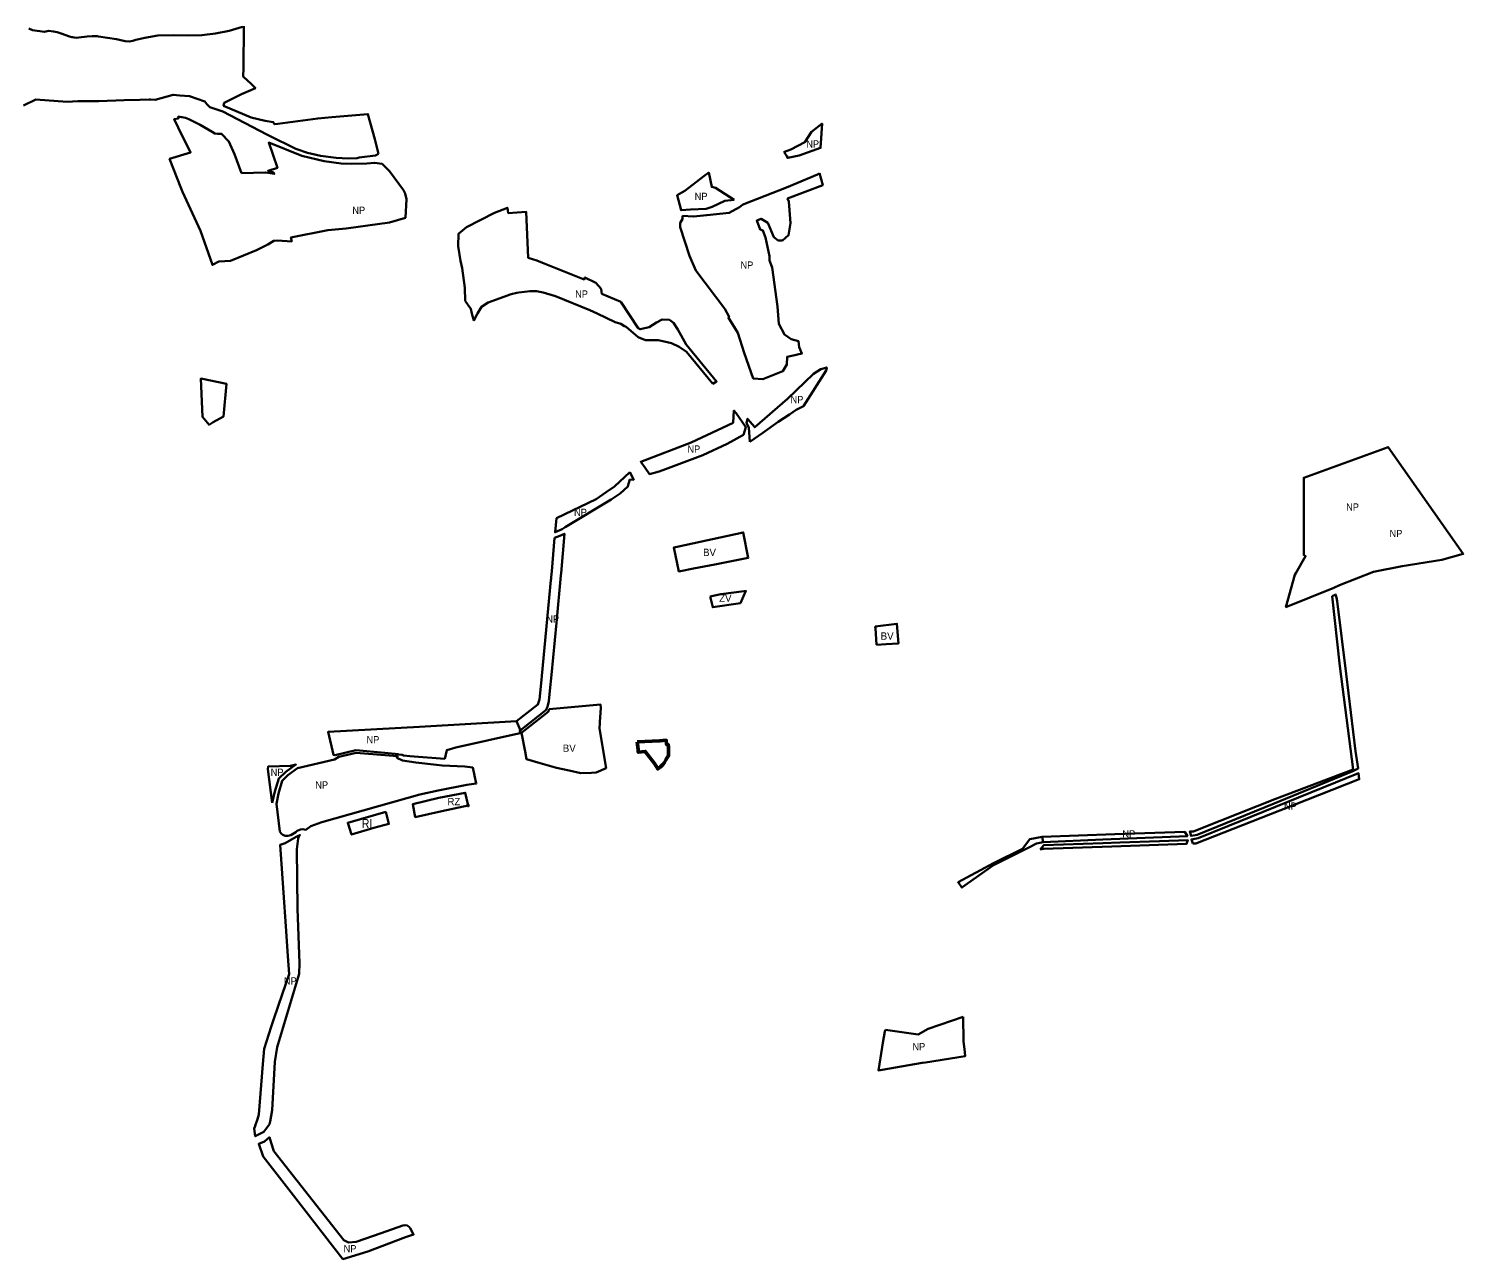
# Model space of a CAD drawing. Extents: x -650276 to -642489, y -1074311 to -1066658.
# Drawn here: x -644867 to -642489, y -1070907 to -1068866 of the extents above; entities that cross this region are included whole.
import ezdxf

# ---------------------------------------------------------------- set-up
doc = ezdxf.new("R2010")
doc.units = 0
doc.header["$LTSCALE"] = 4.8
doc.header["$PDMODE"] = 32
doc.header["$PDSIZE"] = 2.4
for name, color, linetype, lineweight in [('15', 7, 'Continuous', 35), ('3', 7, 'Continuous', 35), ('40', 7, 'Continuous', 35), ('48', 7, 'Continuous', 35), ('6', 7, 'Continuous', 35), ('60', 7, 'Continuous', 53), ('8', 7, 'Continuous', 35)]:
    doc.layers.add(name, color=color, linetype=linetype, lineweight=lineweight)
doc.layers.add('62', color=7, linetype='Continuous')

msp = doc.modelspace()

# ---------------------------------------------------------------- linework, layer by layer
at = {"layer": '15', "lineweight": 13}
for points in [[(-643461.327, -1069887.84), (-643445.37, -1069886.7), (-643425.253, -1069885.25), (-643427.6, -1069852.59), (-643463.51, -1069857.44)], [(-643463.51, -1069857.44), (-643463.31, -1069860.18), (-643461.327, -1069887.84)]]:
    msp.add_lwpolyline(points, dxfattribs=at)
at = {"layer": '3'}
for points in [[(-643791.88, -1069725.25), (-643797.75, -1069726.51), (-643789.3, -1069766.05), (-643786.35, -1069765.46), (-643764.94, -1069761.27), (-643729.34, -1069754.3), (-643674.3, -1069743.53), (-643682.61, -1069701.16)], [(-643461.327, -1069887.84), (-643445.37, -1069886.7), (-643425.253, -1069885.25), (-643427.6, -1069852.59), (-643463.51, -1069857.44), (-643463.31, -1069860.18)], [(-643920.84, -1070026.46), (-643920.29, -1070017.73), (-643920.16, -1070015.69), (-643918.69, -1069992.23), (-643918.88, -1069986.82), (-644004.06, -1069994.59), (-644005.92, -1069998.62), (-644044.7, -1070029.04), (-644050.12, -1070033.64), (-644044.18, -1070064.43), (-644041.71, -1070077.29), (-644022.77, -1070082.66), (-643991.99, -1070091.37), (-643971.03, -1070095.79), (-643951.99, -1070100.35), (-643933.96, -1070100.18), (-643926.33, -1070099.5), (-643909.87, -1070091.95)]]:
    msp.add_lwpolyline(points, close=True, dxfattribs=at)
at = {"layer": '40'}
msp.add_lwpolyline([(-643737.47, -1069807.24), (-643733.02, -1069825.4), (-643687.2, -1069818.8), (-643680.15, -1069803.22), (-643678.02, -1069798.52), (-643680.83, -1069798.86), (-643719.42, -1069803.49)], close=True, dxfattribs=at)
at = {"layer": '48'}
msp.add_line((-644015.12, -1069254.24), (-644024.93, -1069250.23), dxfattribs=at)
for points in [[(-644783.84, -1068880.69), (-644787.7, -1068880.94), (-644791.66, -1068880.72), (-644794.33, -1068880.25), (-644795.57, -1068880.03), (-644799.27, -1068878.92), (-644813.52, -1068873.69), (-644819.79, -1068871.79), (-644826.24, -1068870.62), (-644834.48, -1068869.6), (-644840.86, -1068870.9), (-644861.04, -1068868.43), (-644867.05, -1068865.58)], [(-644512.71, -1068863.06), (-644534.67, -1068869.62), (-644557.21, -1068874.19), (-644580.06, -1068876.69), (-644602.97, -1068877.11), (-644626.34, -1068876.48), (-644653.09, -1068877.33), (-644674.5, -1068880.97), (-644689.63, -1068884.43), (-644694.39, -1068886.08), (-644700.83, -1068886.97), (-644707.32, -1068886.63), (-644721.29, -1068883.2), (-644751.36, -1068878.76), (-644753.71, -1068878.41), (-644761.63, -1068878.43), (-644770.17, -1068879.01), (-644783.84, -1068880.69)], [(-644286.94, -1069073.19), (-644293.51, -1069049.01), (-644304.6, -1069007.55), (-644364.53, -1069012.83), (-644387.91, -1069014.64), (-644453.95, -1069023.63), (-644459.67, -1069024.41), (-644461.74, -1069020.83), (-644475.09, -1069018.99), (-644498.28, -1069013.19), (-644544.02, -1068993.75), (-644543.05, -1068988.64), (-644523.4, -1068978.98), (-644519.61, -1068977.02), (-644514.16, -1068974.62), (-644491.31, -1068964.35), (-644496.63, -1068959.11), (-644498.8, -1068956.97), (-644503.61, -1068952.56), (-644511.47, -1068945.37), (-644510.75, -1068931.16), (-644510.37, -1068861.95)], [(-644657.61, -1068983.91), (-644627.41, -1068975.6), (-644616.36, -1068976.86), (-644600.67, -1068977.77), (-644575.29, -1068986.48), (-644572.05, -1068991.08), (-644567.09, -1068996.26), (-644545.54, -1069003.12), (-644472.37, -1069041.44), (-644468.95, -1069043.11), (-644424.01, -1069065.01), (-644404.96, -1069071.76), (-644383.55, -1069076.57), (-644357.4, -1069079.84), (-644337.6, -1069081.29), (-644322.55, -1069080.62), (-644319.2, -1069079.82), (-644292.27, -1069076.05), (-644286.94, -1069073.19)], [(-644875.57, -1068993.47), (-644855.56, -1068983.38), (-644803.31, -1068986.97), (-644785.78, -1068986.13), (-644761.88, -1068986.27), (-644750.67, -1068986.34), (-644708.6, -1068984.54), (-644683, -1068984.03), (-644667.57, -1068983.47), (-644665.41, -1068983.39), (-644657.61, -1068983.91)], [(-644619.1, -1069011.81), (-644618.8, -1069014.7), (-644625.69, -1069015.84)], [(-644625.69, -1069015.84), (-644619.54, -1069029.55), (-644598.81, -1069071.02)], [(-644583.05, -1069025.29), (-644601.43, -1069015.74), (-644607.16, -1069013.56), (-644619.1, -1069011.81)], [(-644553.62, -1069040.53), (-644558.56, -1069039.86), (-644563.19, -1069037.21), (-644583.05, -1069025.29)], [(-644535.13, -1069053.18), (-644547.31, -1069040.11), (-644553.62, -1069040.53)], [(-644598.81, -1069071.02), (-644633.66, -1069082), (-644614.41, -1069131.08), (-644612.3, -1069136.45), (-644582.29, -1069201.27), (-644562.47, -1069257.56), (-644552.01, -1069252.24), (-644541.83, -1069251.66), (-644532.71, -1069251.12), (-644489.27, -1069233.04), (-644470.64, -1069224), (-644460.97, -1069217.61)], [(-644514.47, -1069105.62), (-644525.83, -1069073.84), (-644535.13, -1069053.18)], [(-644281.26, -1069090.19), (-644293.62, -1069088.17), (-644306.29, -1069089.37), (-644331.44, -1069090), (-644349.32, -1069089.22), (-644377.36, -1069085.89), (-644414.04, -1069076.75), (-644469.28, -1069054.8), (-644454.75, -1069096.51)], [(-644454.75, -1069096.51), (-644470.37, -1069101.55), (-644461.01, -1069104.36), (-644459.82, -1069106.73), (-644474.33, -1069104.22), (-644514.47, -1069105.62)], [(-644242.48, -1069179.49), (-644240.67, -1069148.58), (-644243.14, -1069139.47), (-644245.65, -1069133.66), (-644269.11, -1069102.31), (-644281.26, -1069090.19)], [(-643697.29, -1069149.7), (-643728.49, -1069129.95), (-643734.75, -1069128.3), (-643739.66, -1069104.58), (-643747.75, -1069110.71), (-643779.31, -1069134.63), (-643784.55, -1069137.77), (-643792.04, -1069142.27), (-643785.6, -1069166.98), (-643769.71, -1069166.04)], [(-643555.98, -1069105.57), (-643559.5, -1069107.98), (-643610.81, -1069129.04), (-643681.63, -1069157.04), (-643683.68, -1069157.86), (-643688.91, -1069162.16), (-643705.7, -1069171.37), (-643743.11, -1069175.08), (-643764.86, -1069177.58), (-643782.92, -1069176.24)], [(-643607.02, -1069152.34), (-643609.08, -1069147.64), (-643550.79, -1069125.24), (-643555.98, -1069105.57)], [(-644024.93, -1069250.23), (-644038.83, -1069245.65), (-644042.37, -1069169.77), (-644071.97, -1069171.72), (-644073.35, -1069162.84), (-644094.79, -1069171.27)], [(-643769.71, -1069166.04), (-643743.99, -1069164.43), (-643733.83, -1069161.46), (-643712.74, -1069151.46), (-643697.29, -1069149.7)], [(-643707.23, -1069344.52), (-643691.6, -1069370.3), (-643681.09, -1069403.24), (-643665.87, -1069446.1), (-643650.28, -1069446.91), (-643616.78, -1069433.81), (-643610.18, -1069422.91), (-643609.6, -1069409.99), (-643601.9, -1069408.43), (-643585.19, -1069404.76), (-643589.52, -1069393.88), (-643590.89, -1069383.9), (-643602.92, -1069380.53), (-643614.35, -1069373.28), (-643623.28, -1069355.47), (-643625.9, -1069326.77), (-643634.56, -1069262.02), (-643639.23, -1069250.38), (-643638.72, -1069242.94), (-643645.61, -1069212.25), (-643649.84, -1069200.4), (-643654.57, -1069198.77), (-643660.22, -1069184.11), (-643653.05, -1069180.98), (-643641.84, -1069187.68), (-643631.66, -1069211.67), (-643624.38, -1069217.27), (-643617.64, -1069217), (-643607.37, -1069208.43), (-643604.38, -1069188.48), (-643607.02, -1069152.34)], [(-644460.97, -1069217.61), (-644454.87, -1069217.05), (-644430.91, -1069218.82), (-644432.53, -1069212.02), (-644371.08, -1069199.84), (-644340.83, -1069197.13), (-644268.7, -1069187.42), (-644242.48, -1069179.49)], [(-644094.79, -1069171.27), (-644141.24, -1069195.17), (-644154.36, -1069206.06), (-644155.37, -1069226.72), (-644151.11, -1069250.7), (-644148.22, -1069263.22), (-644144.05, -1069295.67)], [(-643782.92, -1069176.24), (-643783.2, -1069181.85), (-643786.97, -1069188.11), (-643786.89, -1069195.02), (-643771.86, -1069242.77), (-643761.21, -1069267.12), (-643712.78, -1069330.24)], [(-643732.705, -1069454.79), (-643726.74, -1069450.72), (-643777.27, -1069389.71), (-643791.02, -1069364.54), (-643798.1, -1069353.51), (-643804.83, -1069348.99), (-643817.06, -1069348.14), (-643826.21, -1069352.92), (-643838.69, -1069360.79), (-643853.56, -1069364.44), (-643856.43, -1069362.68), (-643885.63, -1069318.72), (-643916.78, -1069305.89), (-643917.36, -1069302.04), (-643918.08, -1069297.33), (-643926.74, -1069287.37), (-643944.89, -1069278.32), (-643946.16, -1069281.84), (-644015.12, -1069254.24)], [(-644144.05, -1069295.67), (-644143.54, -1069317.05), (-644138.55, -1069324.23), (-644134.15, -1069330.45), (-644132.52, -1069338.02), (-644129.09, -1069349.83), (-644123.21, -1069338.41), (-644116.33, -1069327.36), (-644105.5, -1069320.03), (-644067.08, -1069306.15), (-644058.05, -1069304.02), (-644054.35, -1069303.55)], [(-644054.35, -1069303.55), (-644035.89, -1069301.02), (-644025.24, -1069301.38), (-644014.19, -1069303.36), (-643993.91, -1069309.57), (-643936.87, -1069332.93), (-643924.42, -1069338.29), (-643894.84, -1069352.76), (-643885.22, -1069355.58), (-643879.48, -1069359.13), (-643876.34, -1069360.61), (-643856.58, -1069377.59), (-643844.28, -1069382.26), (-643823.72, -1069382.61), (-643815.93, -1069384.23), (-643801.36, -1069387.23), (-643788.63, -1069393.7), (-643776.78, -1069401.87), (-643732.705, -1069454.79)], [(-643712.78, -1069330.24), (-643705.74, -1069343.54), (-643707.23, -1069344.52)], [(-644058.55, -1070014.4), (-644219.33, -1070023.53), (-644370.87, -1070032.13), (-644361.74, -1070070.32), (-644359.02, -1070070.67), (-644324.72, -1070062.44), (-644276.85, -1070066.62), (-644254.13, -1070069.08)], [(-644177.01, -1070076.69), (-644177.01, -1070076.69), (-644174.12, -1070062.16), (-644159.02, -1070057.84), (-644050.12, -1070033.64), (-644053.18, -1070030.57), (-644051.913, -1070029.549), (-644058.55, -1070014.4)], [(-644254.13, -1070069.08), (-644254.25, -1070069.37), (-644247.72, -1070070.21), (-644245.9, -1070071.26), (-644235.49, -1070072.08), (-644177.01, -1070076.69)], [(-643452.22, -1070592.35), (-643385.72, -1070580.86), (-643380.35, -1070580.14), (-643380.08, -1070580.09), (-643314.51, -1070569.69), (-643315.27, -1070563.2), (-643317.08, -1070544.75), (-643317.9, -1070504.73)], [(-643446.89, -1070526.01), (-643447.79, -1070528.63), (-643450.98, -1070547.74), (-643452.14, -1070554.77)], [(-643317.9, -1070504.73), (-643376.07, -1070524.59), (-643392.41, -1070533.68), (-643446.89, -1070526.01)], [(-643452.14, -1070554.77), (-643458.42, -1070593.43), (-643452.22, -1070592.35)]]:
    msp.add_lwpolyline(points, dxfattribs=at)
for points in [[(-644514.47, -1069105.62), (-644474.33, -1069104.22), (-644459.82, -1069106.73), (-644461.01, -1069104.36), (-644470.37, -1069101.55), (-644454.75, -1069096.51), (-644469.28, -1069054.8), (-644414.04, -1069076.75), (-644377.36, -1069085.89), (-644349.32, -1069089.22), (-644331.44, -1069090), (-644306.29, -1069089.37), (-644293.62, -1069088.17), (-644281.26, -1069090.19), (-644269.11, -1069102.31), (-644245.65, -1069133.66), (-644243.14, -1069139.47), (-644240.67, -1069148.58), (-644242.48, -1069179.49), (-644268.7, -1069187.42), (-644340.83, -1069197.13), (-644371.08, -1069199.84), (-644432.53, -1069212.02), (-644430.91, -1069218.82), (-644454.87, -1069217.05), (-644460.97, -1069217.61), (-644470.64, -1069224), (-644489.27, -1069233.04), (-644532.71, -1069251.12), (-644541.83, -1069251.66), (-644552.01, -1069252.24), (-644562.47, -1069257.56), (-644582.29, -1069201.27), (-644612.3, -1069136.45), (-644614.41, -1069131.08), (-644633.66, -1069082), (-644598.81, -1069071.02), (-644619.54, -1069029.55), (-644625.69, -1069015.84), (-644618.8, -1069014.7), (-644619.1, -1069011.81), (-644607.16, -1069013.56), (-644601.43, -1069015.74), (-644583.05, -1069025.29), (-644563.19, -1069037.21), (-644558.56, -1069039.86), (-644553.62, -1069040.53), (-644547.31, -1069040.11), (-644535.13, -1069053.18), (-644525.83, -1069073.84)], [(-643589.94, -1069076.36), (-643554.17, -1069063.59), (-643551.72, -1069023.19), (-643569.44, -1069037.24), (-643580.21, -1069053.96), (-643603.72, -1069066.5), (-643614.36, -1069070.29), (-643614.82, -1069070.45), (-643610.31, -1069077.52), (-643608.65, -1069080.11)], [(-643671.53, -1069551.1), (-643649.94, -1069535.93), (-643624.65, -1069517.85), (-643605.97, -1069505.47), (-643594.49, -1069498.17), (-643582.77, -1069491.76), (-643545.07, -1069432.89), (-643544.06, -1069427.6), (-643553.7, -1069430.44), (-643565.92, -1069438.4), (-643608.89, -1069479.72), (-643663.46, -1069526.87), (-643675.32, -1069512.62), (-643676.9, -1069519.91), (-643673.34, -1069527.08)], [(-644578.92, -1069446.8), (-644539, -1069454.88), (-644543.99, -1069508.88), (-644561.24, -1069518.27), (-644567.976, -1069522.752), (-644579.047, -1069509.608), (-644581.87, -1069446.28)], [(-644578.92, -1069446.8), (-644581.87, -1069446.28), (-644579.047, -1069509.608), (-644567.976, -1069522.752), (-644561.24, -1069518.27), (-644543.99, -1069508.88), (-644539, -1069454.88)], [(-643845.304, -1069594.087), (-643837.72, -1069604.62), (-643822.06, -1069600.07), (-643811.16, -1069596.45), (-643749.64, -1069573.35), (-643709.33, -1069554.14), (-643682.27, -1069539.41), (-643678.24, -1069526.44), (-643693.95, -1069503.38), (-643697.85, -1069499.21), (-643699.23, -1069519.48), (-643769.08, -1069551.96), (-643852.51, -1069584.08)], [(-642589.86, -1069757.1), (-642524.14, -1069746.8), (-642488.71, -1069736.85), (-642613.34, -1069559.68), (-642753.18, -1069610.65), (-642753.25, -1069738.59), (-642750.08, -1069740.57), (-642766.27, -1069769), (-642767.89, -1069771.42), (-642782.69, -1069824.93), (-642703.57, -1069792.88), (-642693.99, -1069788.85), (-642637.44, -1069766.81)], [(-643870.697, -1069601.241), (-643895.951, -1069625.069), (-643909.616, -1069634.267), (-643926.229, -1069646.367), (-643992.34, -1069677.76), (-643994.36, -1069701.05), (-643982.84, -1069695.93), (-643977.582, -1069692.76), (-643901.55, -1069646.92), (-643886.62, -1069636.87), (-643873.82, -1069625.05), (-643872.55, -1069620.75), (-643870.44, -1069613.56), (-643863.92, -1069613.9)], [(-643995.17, -1069710.42), (-643999.94, -1069765.62), (-644000.79, -1069775.42), (-644001.04, -1069778.063), (-644001.29, -1069780.7), (-644016.47, -1069938.99), (-644017.15, -1069945.93), (-644020.26, -1069978.38), (-644022.43, -1069984.87), (-644022.99, -1069986.58), (-644058.55, -1070014.4), (-644051.913, -1070029.549), (-644049.311, -1070027.453), (-644009.95, -1069995.74), (-644006.96, -1069990.34), (-644005.06, -1069981.28), (-644003.06, -1069964.06), (-644000.52, -1069937.19), (-643992.27, -1069851.31), (-643984.845, -1069772.863), (-643984.44, -1069768.58), (-643978.85, -1069703.4), (-643986.744, -1069706.796)], [(-642706.3, -1069806.69), (-642693.2, -1069922.89), (-642671.23, -1070094.16), (-642801.19, -1070143.75), (-642921.03, -1070191.32), (-642936.02, -1070197.23), (-642942.12, -1070197.4), (-642940.12, -1070204.42), (-642930.02, -1070202.54), (-642802.38, -1070150.51), (-642671.9, -1070097.32), (-642663.28, -1070092.67), (-642667.19, -1070063.71), (-642682.78, -1069935.98), (-642697.64, -1069815.14), (-642698.77, -1069809.17), (-642700.34, -1069804.12), (-642701.17, -1069804.49)], [(-644381.21, -1070181.71), (-644218.65, -1070135.75), (-644188.44, -1070129.43), (-644140.72, -1070119.57), (-644125, -1070117.83), (-644130.91, -1070091.1), (-644144.13, -1070089.47), (-644181.81, -1070087.51), (-644191.26, -1070086.47), (-644225.13, -1070082.95), (-644247.3, -1070079.69), (-644256.54, -1070075.02), (-644255.52, -1070072.5), (-644324.42, -1070066.48), (-644352.71, -1070073.46), (-644360.41, -1070077.91), (-644421.26, -1070091.99), (-644437.34, -1070103.76), (-644447.13, -1070113.11), (-644453.22, -1070133.99), (-644456.41, -1070151.18), (-644450.72, -1070196.97), (-644448.76, -1070200.77), (-644445.9, -1070202.83), (-644441.8, -1070204.26), (-644437.415, -1070204.436), (-644432.53, -1070203.32), (-644424.14, -1070198.29), (-644421.88, -1070196.28), (-644419.51, -1070194.76), (-644416.67, -1070193.7), (-644412.54, -1070193.18), (-644407.55, -1070194.16), (-644399.15, -1070188.55)], [(-644463.28, -1070149.42), (-644459.09, -1070131.08), (-644452.65, -1070109.46), (-644440.64, -1070098.4), (-644423.99, -1070086.17), (-644433.19, -1070088.37), (-644470.17, -1070089.43), (-644470.55, -1070093.61)], [(-642936.88, -1070217.27), (-642931.88, -1070217.1), (-642792.87, -1070162.36), (-642661.13, -1070110.48), (-642662.32, -1070100.64), (-642879.2, -1070188.43), (-642928.07, -1070208.21), (-642939.51, -1070210.35)], [(-644491.691, -1070685.524), (-644491.82, -1070685.92), (-644493.5, -1070689.75), (-644491.42, -1070702.64), (-644477.46, -1070695.09), (-644467.84, -1070682.37), (-644466.998, -1070678.065), (-644463.28, -1070659.06), (-644458.85, -1070579.04), (-644455.2, -1070554.88), (-644418.69, -1070433.36), (-644418.23, -1070415.62), (-644421.45, -1070325.29), (-644422.5, -1070226.42), (-644420.14, -1070208.56), (-644418.61, -1070204.51), (-644417.36, -1070203.24), (-644421.47, -1070204.77), (-644423.66, -1070205.86), (-644442.2, -1070216.72), (-644450.15, -1070219.06), (-644445.28, -1070290.84), (-644440.36, -1070362.62), (-644437.53, -1070404.1), (-644435.51, -1070433.85), (-644447.14, -1070467.28), (-644460.5, -1070507.68), (-644464.98, -1070521.13), (-644476.94, -1070557.45), (-644479.06, -1070583.13), (-644485.64, -1070666.7), (-644488.01, -1070674.2)], [(-643185.16, -1070214.62), (-643187.06, -1070205.98), (-643207.1, -1070209.72), (-643219.4, -1070225.8), (-643267.55, -1070249.49), (-643326.26, -1070281.43), (-643320, -1070290.2), (-643267.75, -1070252.77), (-643208.09, -1070223.14), (-643196.16, -1070217.22)], [(-643190.42, -1070226.99), (-643184.86, -1070225.91), (-643071.16, -1070221.95), (-642947.42, -1070217.64), (-642945.59, -1070211.49), (-642992.64, -1070213.18), (-643058.07, -1070215.38), (-643086.58, -1070216.57), (-643184.22, -1070220.08)], [(-643066.26, -1070201.69), (-643187.06, -1070205.98), (-643185.16, -1070214.62), (-643086.36, -1070210.57), (-642946.24, -1070204.83), (-642950.42, -1070197.58)], [(-644346.21, -1070906.61), (-644305.07, -1070893.39), (-644242.29, -1070869.82), (-644229.12, -1070865.52), (-644234.66, -1070855.08), (-644236.3, -1070852.87), (-644239.47, -1070850.71), (-644243.15, -1070849.89), (-644246.93, -1070850.52), (-644282.77, -1070863.19), (-644324.34, -1070877.71), (-644337.15, -1070878.64), (-644344.86, -1070875.09), (-644460.82, -1070727.21), (-644465.31, -1070713.25), (-644468.1, -1070704.23), (-644476.35, -1070710.99), (-644485.61, -1070714.95), (-644478.67, -1070736.28), (-644424.37, -1070806.03)]]:
    msp.add_lwpolyline(points, close=True, dxfattribs=at)
at = {"layer": '6'}
msp.add_lwpolyline([(-644275.05, -1070164.59), (-644338.06, -1070182.64), (-644331.9, -1070202.4), (-644295.01, -1070190.9), (-644269.84, -1070184.57)], close=True, dxfattribs=at)
at = {"layer": '60'}
msp.add_lwpolyline([(-643858.23, -1070048.35), (-643856.72, -1070061.26), (-643856.49, -1070065.66), (-643844.87, -1070064.51), (-643829.38, -1070084.37), (-643824.22, -1070093.34), (-643819.67, -1070089.82), (-643815.9, -1070086.27), (-643813.21, -1070082.8), (-643810.91, -1070078.63), (-643806.17, -1070071.18), (-643806.59, -1070057.37), (-643806.86, -1070053.03), (-643809.71, -1070053.15), (-643810, -1070046), (-643820.78, -1070046.59)], close=True, dxfattribs=at)
at = {"layer": '8'}
for p, q in [((-644138.78, -1070154.07), (-644143.31, -1070132.95)), ((-644182.31, -1070163.66), (-644138.78, -1070154.07))]:
    msp.add_line(p, q, dxfattribs=at)
msp.add_lwpolyline([(-644143.31, -1070132.95), (-644143.31, -1070132.95), (-644143.31, -1070132.95), (-644187.11, -1070141.58), (-644230.4, -1070152.08), (-644226.23, -1070173.28), (-644182.31, -1070163.66)], dxfattribs=at)
msp.add_point((-644138.78, -1070154.07), dxfattribs=at)

# ---------------------------------------------------------------- texts
at = {"layer": '62'}
for s, height, width, p in [('NP', 12, 0.95, (-643577.985, -1069062.967)), ('NP', 12, 0.95, (-643762.985, -1069149.967)), ('NP', 12, 0.95, (-644330.583, -1069173.041)), ('NP', 12, 0.95, (-643686.985, -1069263.967)), ('NP', 12, 0.95, (-643961.069, -1069311.925)), ('NP', 12, 0.95, (-643603.985, -1069486.967)), ('NP', 12, 0.95, (-643774.985, -1069568.967)), ('NP', 12, 0.95, (-643962.985, -1069673.967)), ('NP', 12, 0.95, (-642682.928, -1069665.096)), ('NP', 12, 0.95, (-642610.928, -1069709.096)), ('NP', 12, 0.95, (-644008.985, -1069850.967)), ('NP', 12, 0.95, (-644306.985, -1070050.967)), ('NP', 12, 0.95, (-644465.985, -1070104.967)), ('NP', 12, 0.95, (-644391.985, -1070125.967)), ('NP', 12, 0.95, (-642785.928, -1070161.096)), ('RI', 15, 0.85, (-644314.705, -1070191.481)), ('NP', 12, 0.95, (-643053.928, -1070207.096)), ('NP', 12, 0.95, (-644444, -1070450.967)), ('NP', 12, 0.95, (-643401.985, -1070559.967)), ('NP', 12, 0.95, (-644345, -1070894.967))]:
    msp.add_text(s, height=height, dxfattribs=dict(at, width=width)).set_placement(p)
for s, p in [('BV', (-643749.135, -1069740.303)), ('ZV', (-643722.385, -1069816.315)), ('BV', (-643454.639, -1069879.037)), ('BV', (-643981.639, -1070065.037)), ('RZ', (-644172.882, -1070153.612))]:
    msp.add_text(s, height=12, dxfattribs=at).set_placement(p)

doc.saveas('drawing.dxf')
